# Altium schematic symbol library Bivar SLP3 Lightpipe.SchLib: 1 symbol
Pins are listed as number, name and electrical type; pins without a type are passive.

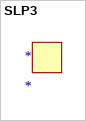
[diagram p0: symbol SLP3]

## SLP3
designator *
footprint PCBComponent_1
